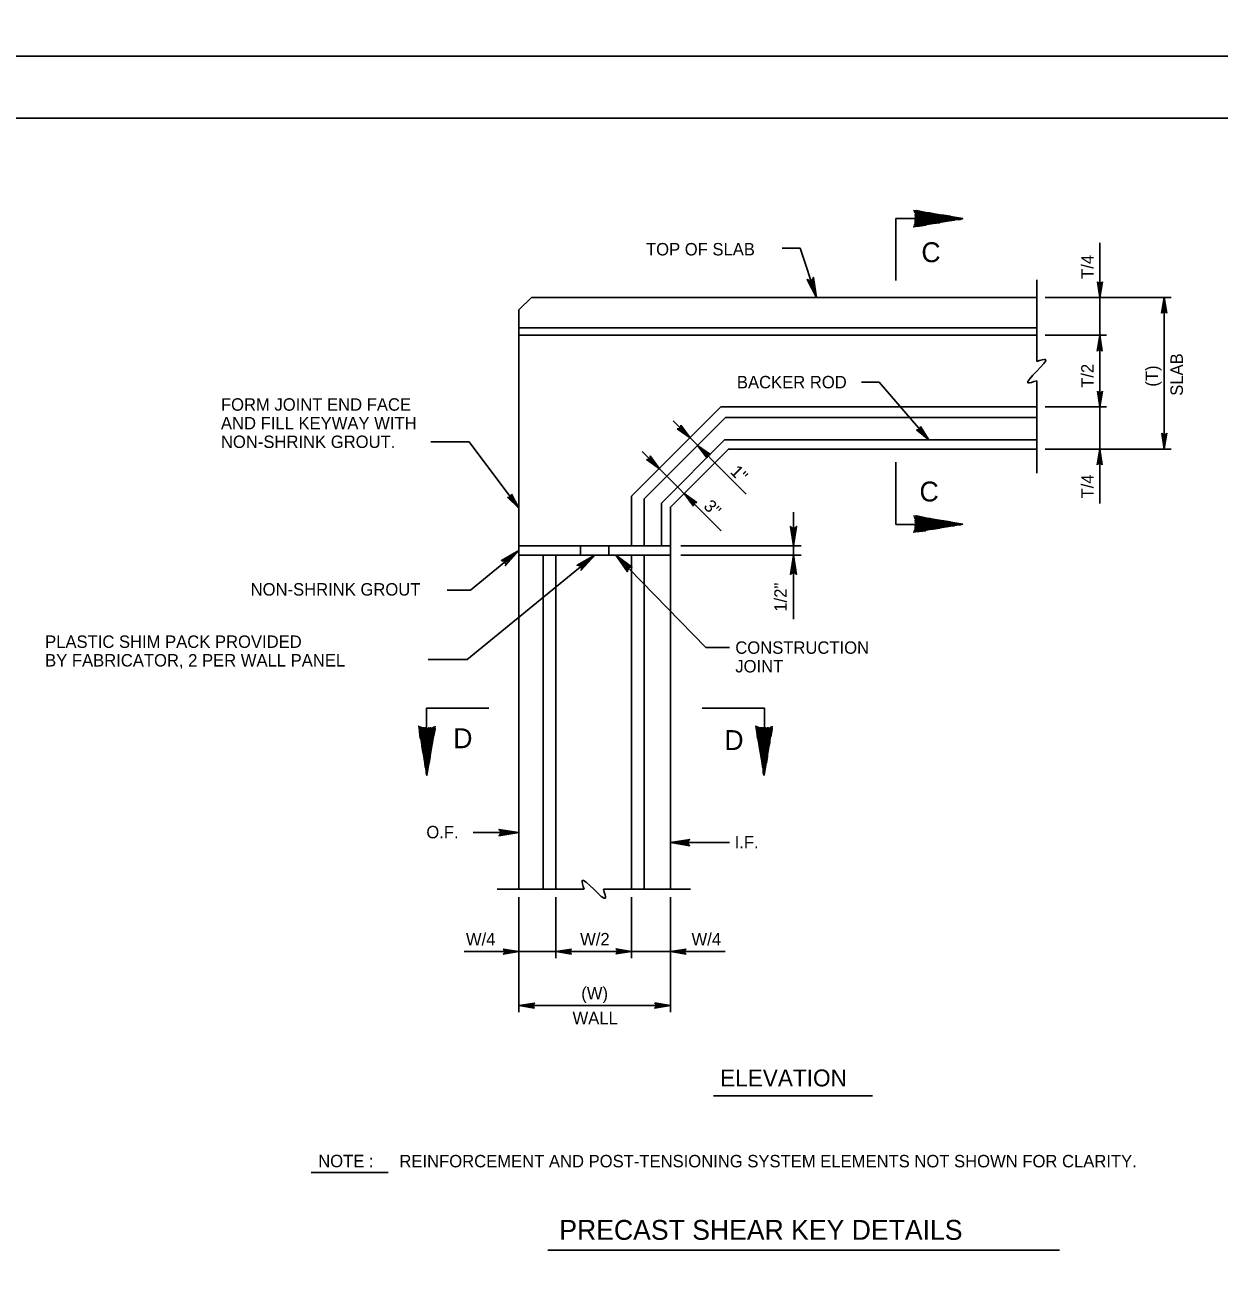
# Model space of a CAD drawing. Extents: x 641328 to 643024, y 298283 to 300065.
# Drawn here: x 641559 to 641847.3, y 298583 to 298884.8 of the extents above; entities that cross this region are included whole.
import ezdxf

# ---------------------------------------------------------------- set-up
doc = ezdxf.new("R2010")
doc.units = 0
for name, color, linetype in [('2', 7, 'Continuous'), ('40', 7, 'Continuous'), ('63', 7, 'Continuous'), ('Default', 7, 'Continuous'), ('PLT-BNDY', 7, 'Continuous')]:
    doc.layers.add(name, color=color, linetype=linetype)

msp = doc.modelspace()

# ---------------------------------------------------------------- linework, layer by layer
at = {"layer": '2'}
for p, q in [((641367.51, 298862.3), (642153.5, 298862.3)), ((641769.25, 298838.11), (641769.25, 298823.08)), ((641769.25, 298838.11), (641784.28, 298838.11)), ((641818.54, 298809.88), (641818.54, 298832.18)), ((641746.21, 298830.93), (641750.15, 298819)), ((641803.33, 298803.54), (641803.33, 298823.25)), ((641818.11, 298822.61), (641817.95, 298822.8)), ((641817.95, 298822.8), (641818.54, 298819)), ((641818.11, 298822.61), (641818.37, 298822.47)), ((641818.54, 298819), (641818.11, 298822.61)), ((641818.37, 298822.47), (641818.54, 298819)), ((641818.37, 298822.47), (641818.74, 298822.47)), ((641818.54, 298819), (641819.17, 298822.8)), ((641819, 298822.6), (641818.54, 298819)), ((641818.54, 298819), (641818.74, 298822.47)), ((641818.54, 298819), (641818.56, 298822.47)), ((641818.74, 298822.47), (641819, 298822.6)), ((641819.17, 298822.8), (641819, 298822.6)), ((641678.26, 298816), (641681.26, 298819)), ((641678.26, 298816), (641678.26, 298676.24)), ((641803.33, 298819), (641681.26, 298819)), ((641805.35, 298819), (641835.74, 298819)), ((641834.11, 298819), (641833.48, 298815.21)), ((641833.65, 298815.4), (641834.11, 298819)), ((641834.11, 298819), (641833.91, 298815.53)), ((641834.11, 298819), (641834.1, 298815.53)), ((641834.11, 298782.43), (641834.11, 298819)), ((641834.28, 298815.53), (641834.11, 298819)), ((641834.11, 298819), (641834.54, 298815.39)), ((641834.7, 298815.2), (641834.11, 298819)), ((641833.48, 298815.21), (641833.65, 298815.4)), ((641833.91, 298815.53), (641833.65, 298815.4)), ((641834.28, 298815.53), (641833.91, 298815.53)), ((641834.54, 298815.39), (641834.28, 298815.53)), ((641834.54, 298815.39), (641834.7, 298815.2)), ((641803.33, 298811.65), (641678.26, 298811.65)), ((641803.33, 298809.88), (641678.26, 298809.88)), ((641805.35, 298809.88), (641820.17, 298809.88)), ((641818.54, 298809.88), (641817.91, 298806.08)), ((641818.08, 298806.28), (641818.54, 298809.88)), ((641818.54, 298809.88), (641818.34, 298806.4)), ((641818.54, 298809.88), (641818.53, 298806.4)), ((641818.54, 298792.58), (641818.54, 298809.88)), ((641818.71, 298806.4), (641818.54, 298809.88)), ((641818.54, 298809.88), (641818.97, 298806.27)), ((641819.13, 298806.07), (641818.54, 298809.88)), ((641817.91, 298806.08), (641818.08, 298806.28)), ((641818.34, 298806.4), (641818.08, 298806.28)), ((641818.71, 298806.4), (641818.34, 298806.4)), ((641818.97, 298806.27), (641818.71, 298806.4)), ((641818.97, 298806.27), (641819.13, 298806.07)), ((641765.24, 298798.56), (641760.96, 298798.56)), ((641777.24, 298784.61), (641765.24, 298798.56)), ((641803.33, 298776.57), (641803.33, 298798.92)), ((641818.11, 298796.19), (641817.95, 298796.38)), ((641817.95, 298796.38), (641818.54, 298792.58)), ((641818.11, 298796.19), (641818.37, 298796.05)), ((641818.54, 298792.58), (641818.11, 298796.19)), ((641818.37, 298796.05), (641818.54, 298792.58)), ((641818.37, 298796.05), (641818.74, 298796.05)), ((641818.54, 298792.58), (641819.17, 298796.37)), ((641819, 298796.18), (641818.54, 298792.58)), ((641818.54, 298792.58), (641818.74, 298796.05)), ((641818.54, 298792.58), (641818.56, 298796.05)), ((641818.74, 298796.05), (641819, 298796.18)), ((641819.17, 298796.37), (641819, 298796.18)), ((641705.47, 298771.04), (641727.01, 298792.58)), ((641803.33, 298792.58), (641727.01, 298792.58)), ((641805.35, 298792.58), (641820.17, 298792.58)), ((641818.54, 298769.31), (641818.54, 298792.58)), ((641708.52, 298770.42), (641728.15, 298790.05)), ((641733.15, 298771.57), (641715.47, 298789.25)), ((641803.33, 298790.05), (641728.15, 298790.05)), ((641719.62, 298785.1), (641716.49, 298787.33)), ((641716.49, 298787.33), (641716.75, 298787.32)), ((641717.03, 298787.41), (641716.75, 298787.32)), ((641716.75, 298787.32), (641719.62, 298785.1)), ((641717.28, 298787.67), (641717.03, 298787.41)), ((641719.62, 298785.1), (641717.03, 298787.41)), ((641719.62, 298785.1), (641717.15, 298787.54)), ((641717.37, 298787.95), (641717.28, 298787.67)), ((641717.28, 298787.67), (641719.62, 298785.1)), ((641717.37, 298787.95), (641717.35, 298788.2)), ((641717.35, 298788.2), (641719.62, 298785.1)), ((641719.62, 298785.1), (641717.37, 298787.95)), ((641777.24, 298784.61), (641774.3, 298787.09)), ((641774.3, 298787.09), (641774.56, 298787.05)), ((641774.84, 298787.12), (641774.56, 298787.05)), ((641774.56, 298787.05), (641777.24, 298784.61)), ((641775.11, 298787.36), (641774.84, 298787.12)), ((641777.24, 298784.61), (641774.84, 298787.12)), ((641777.24, 298784.61), (641774.98, 298787.24)), ((641775.23, 298787.64), (641775.11, 298787.36)), ((641775.11, 298787.36), (641777.24, 298784.61)), ((641775.23, 298787.64), (641775.22, 298787.89)), ((641775.22, 298787.89), (641777.24, 298784.61)), ((641777.24, 298784.61), (641775.23, 298787.64)), ((641833.68, 298786.03), (641833.52, 298786.23)), ((641833.52, 298786.23), (641834.11, 298782.43)), ((641833.68, 298786.03), (641833.95, 298785.9)), ((641834.11, 298782.43), (641833.68, 298786.03)), ((641833.95, 298785.9), (641834.11, 298782.43)), ((641833.95, 298785.9), (641834.31, 298785.9)), ((641834.11, 298782.43), (641834.75, 298786.22)), ((641834.57, 298786.02), (641834.11, 298782.43)), ((641834.11, 298782.43), (641834.31, 298785.9)), ((641834.11, 298782.43), (641834.13, 298785.9)), ((641834.31, 298785.9), (641834.57, 298786.02)), ((641834.75, 298786.22), (641834.57, 298786.02)), ((641657.01, 298784.18), (641666.25, 298784.18)), ((641666.25, 298784.18), (641678.26, 298768.15)), ((641712.65, 298769.33), (641727.93, 298784.61)), ((641723.75, 298780.73), (641721.41, 298783.31)), ((641721.41, 298783.31), (641723.66, 298780.45)), ((641723.68, 298780.2), (641721.41, 298783.31)), ((641721.41, 298783.31), (641724, 298780.99)), ((641724.28, 298781.09), (641721.41, 298783.31)), ((641721.41, 298783.31), (641724.54, 298781.07)), ((641721.41, 298783.31), (641723.87, 298780.86)), ((641803.33, 298784.61), (641727.93, 298784.61)), ((641727.13, 298762.71), (641708.03, 298781.81)), ((641712.18, 298777.66), (641709.05, 298779.89)), ((641709.05, 298779.89), (641709.31, 298779.88)), ((641709.59, 298779.97), (641709.31, 298779.88)), ((641709.31, 298779.88), (641712.18, 298777.66)), ((641709.84, 298780.23), (641709.59, 298779.97)), ((641712.18, 298777.66), (641709.59, 298779.97)), ((641712.18, 298777.66), (641709.71, 298780.1)), ((641709.93, 298780.51), (641709.84, 298780.23)), ((641709.84, 298780.23), (641712.18, 298777.66)), ((641709.93, 298780.51), (641709.91, 298780.76)), ((641709.91, 298780.76), (641712.18, 298777.66)), ((641712.18, 298777.66), (641709.93, 298780.51)), ((641714.83, 298768.43), (641728.83, 298782.43)), ((641728.83, 298782.43), (641714.83, 298768.43)), ((641723.66, 298780.45), (641723.75, 298780.73)), ((641723.66, 298780.45), (641723.68, 298780.2)), ((641723.75, 298780.73), (641724, 298780.99)), ((641724, 298780.99), (641724.28, 298781.09)), ((641724.54, 298781.07), (641724.28, 298781.09)), ((641728.83, 298782.43), (641803.33, 298782.43)), ((641805.35, 298782.43), (641835.74, 298782.43)), ((641818.54, 298782.43), (641817.91, 298778.63)), ((641818.08, 298778.83), (641818.54, 298782.43)), ((641818.54, 298782.43), (641818.34, 298778.95)), ((641818.54, 298782.43), (641818.53, 298778.95)), ((641818.71, 298778.95), (641818.54, 298782.43)), ((641818.54, 298782.43), (641818.97, 298778.82)), ((641819.13, 298778.62), (641818.54, 298782.43)), ((641769.25, 298764.24), (641769.25, 298779.27)), ((641817.91, 298778.63), (641818.08, 298778.83)), ((641818.34, 298778.95), (641818.08, 298778.83)), ((641818.71, 298778.95), (641818.34, 298778.95)), ((641818.97, 298778.82), (641818.71, 298778.95)), ((641818.97, 298778.82), (641819.13, 298778.62)), ((641678.26, 298768.15), (641675.48, 298770.81)), ((641675.48, 298770.81), (641675.73, 298770.76)), ((641676.02, 298770.81), (641675.73, 298770.76)), ((641675.73, 298770.76), (641678.26, 298768.15)), ((641676.31, 298771.03), (641676.02, 298770.81)), ((641678.26, 298768.15), (641676.02, 298770.81)), ((641678.26, 298768.15), (641676.16, 298770.92)), ((641676.44, 298771.3), (641676.31, 298771.03)), ((641676.31, 298771.03), (641678.26, 298768.15)), ((641676.44, 298771.3), (641676.45, 298771.55)), ((641678.26, 298768.15), (641676.44, 298771.3)), ((641676.45, 298771.55), (641678.26, 298768.15)), ((641705.47, 298759.08), (641705.47, 298771.04)), ((641720.46, 298769.14), (641718.12, 298771.71)), ((641718.12, 298771.71), (641720.37, 298768.86)), ((641720.39, 298768.61), (641718.12, 298771.71)), ((641718.12, 298771.71), (641720.71, 298769.4)), ((641720.99, 298769.49), (641718.12, 298771.71)), ((641718.12, 298771.71), (641721.25, 298769.48)), ((641718.12, 298771.71), (641720.59, 298769.27)), ((641708.52, 298759.08), (641708.52, 298770.42)), ((641712.65, 298769.33), (641712.65, 298759.08)), ((641714.83, 298768.43), (641714.83, 298676.24)), ((641720.37, 298768.86), (641720.46, 298769.14)), ((641720.37, 298768.86), (641720.39, 298768.61)), ((641720.46, 298769.14), (641720.71, 298769.4)), ((641720.71, 298769.4), (641720.99, 298769.49)), ((641721.25, 298769.48), (641720.99, 298769.49)), ((641769.25, 298764.24), (641784.28, 298764.24)), ((641714.83, 298759.08), (641678.26, 298759.08)), ((641714.83, 298759.08), (641678.26, 298759.08)), ((641678.26, 298759.08), (641678.26, 298756.82)), ((641714.83, 298756.82), (641714.83, 298759.08)), ((641717.35, 298759.08), (641746.4, 298759.08)), ((641665.78, 298731.63), (641696.55, 298756.82)), ((641666.58, 298748.38), (641678.26, 298757.95)), ((641678.26, 298756.82), (641714.83, 298756.82)), ((641684.13, 298676.14), (641684.13, 298756.82)), ((641687.18, 298676.14), (641687.18, 298756.82)), ((641723.43, 298734.49), (641701.66, 298756.82)), ((641705.47, 298676.14), (641705.47, 298756.82)), ((641708.52, 298676.14), (641708.52, 298756.82)), ((641717.35, 298756.82), (641746.4, 298756.82)), ((641655.96, 298719.85), (641670.99, 298719.85)), ((641655.96, 298719.85), (641655.96, 298704.82)), ((641737.53, 298719.85), (641722.5, 298719.85)), ((641737.53, 298719.85), (641737.53, 298704.82)), ((641667.22, 298689.84), (641678.26, 298689.84)), ((641714.83, 298687.41), (641729.09, 298687.41)), ((641694.01, 298676.14), (641673.02, 298676.14)), ((641678.26, 298674.2), (641678.26, 298646.44)), ((641687.18, 298674.2), (641687.18, 298659.49)), ((641719.68, 298676.14), (641698.64, 298676.14)), ((641705.47, 298674.2), (641705.47, 298659.49)), ((641714.83, 298674.2), (641714.83, 298646.44)), ((641678.26, 298661.12), (641665, 298661.12)), ((641674.65, 298661.55), (641674.46, 298661.71)), ((641674.46, 298661.71), (641678.26, 298661.12)), ((641678.26, 298661.12), (641674.46, 298660.48)), ((641674.46, 298660.48), (641674.66, 298660.66)), ((641674.65, 298661.55), (641674.78, 298661.28)), ((641678.26, 298661.12), (641674.65, 298661.55)), ((641674.66, 298660.66), (641678.26, 298661.12)), ((641674.79, 298660.92), (641674.66, 298660.66)), ((641674.78, 298661.28), (641678.26, 298661.12)), ((641674.78, 298661.28), (641674.79, 298660.92)), ((641678.26, 298661.12), (641674.79, 298660.92)), ((641678.26, 298661.12), (641674.79, 298661.1)), ((641687.18, 298661.12), (641678.26, 298661.12)), ((641690.98, 298661.71), (641687.18, 298661.12)), ((641687.18, 298661.12), (641690.79, 298661.55)), ((641690.66, 298661.28), (641687.18, 298661.12)), ((641687.18, 298661.12), (641705.47, 298661.12)), ((641687.18, 298661.12), (641690.65, 298660.92)), ((641690.78, 298660.66), (641687.18, 298661.12)), ((641687.18, 298661.12), (641690.98, 298660.48)), ((641687.18, 298661.12), (641690.65, 298661.1)), ((641690.66, 298661.28), (641690.65, 298660.92)), ((641690.65, 298660.92), (641690.78, 298660.66)), ((641690.79, 298661.55), (641690.66, 298661.28)), ((641690.98, 298660.48), (641690.78, 298660.66)), ((641690.79, 298661.55), (641690.98, 298661.71)), ((641701.67, 298660.53), (641705.47, 298661.12)), ((641701.86, 298660.69), (641701.67, 298660.53)), ((641705.47, 298661.12), (641701.68, 298661.75)), ((641701.68, 298661.75), (641701.87, 298661.57)), ((641705.47, 298661.12), (641701.86, 298660.69)), ((641701.86, 298660.69), (641702, 298660.95)), ((641702, 298661.31), (641701.87, 298661.57)), ((641701.87, 298661.57), (641705.47, 298661.12)), ((641705.47, 298661.12), (641702, 298661.31)), ((641702, 298660.95), (641702, 298661.31)), ((641705.47, 298661.12), (641702, 298661.13)), ((641702, 298660.95), (641705.47, 298661.12)), ((641705.47, 298661.12), (641714.83, 298661.12)), ((641718.64, 298661.71), (641714.83, 298661.12)), ((641714.83, 298661.12), (641718.44, 298661.55)), ((641718.31, 298661.28), (641714.83, 298661.12)), ((641714.83, 298661.12), (641718.31, 298660.92)), ((641718.43, 298660.66), (641714.83, 298661.12)), ((641714.83, 298661.12), (641718.63, 298660.48)), ((641714.83, 298661.12), (641718.31, 298661.1)), ((641714.83, 298661.12), (641728.09, 298661.12)), ((641718.44, 298661.55), (641718.31, 298661.28)), ((641718.31, 298661.28), (641718.31, 298660.92)), ((641718.31, 298660.92), (641718.43, 298660.66)), ((641718.63, 298660.48), (641718.43, 298660.66)), ((641718.44, 298661.55), (641718.64, 298661.71)), ((641682.06, 298648.65), (641678.26, 298648.06)), ((641678.26, 298648.06), (641681.87, 298648.49)), ((641681.73, 298648.23), (641678.26, 298648.06)), ((641678.26, 298648.06), (641714.83, 298648.06)), ((641678.26, 298648.06), (641681.73, 298647.87)), ((641681.86, 298647.6), (641678.26, 298648.06)), ((641678.26, 298648.06), (641682.05, 298647.43)), ((641678.26, 298648.06), (641681.73, 298648.05)), ((641681.87, 298648.49), (641681.73, 298648.23)), ((641681.73, 298648.23), (641681.73, 298647.87)), ((641681.73, 298647.87), (641681.86, 298647.6)), ((641682.05, 298647.43), (641681.86, 298647.6)), ((641681.87, 298648.49), (641682.06, 298648.65)), ((641711.03, 298647.47), (641714.83, 298648.06)), ((641711.22, 298647.63), (641711.03, 298647.47)), ((641714.83, 298648.06), (641711.04, 298648.7)), ((641711.04, 298648.7), (641711.24, 298648.52)), ((641714.83, 298648.06), (641711.22, 298647.63)), ((641711.22, 298647.63), (641711.36, 298647.9)), ((641711.36, 298648.26), (641711.24, 298648.52)), ((641711.24, 298648.52), (641714.83, 298648.06)), ((641714.83, 298648.06), (641711.36, 298648.26)), ((641711.36, 298647.9), (641711.36, 298648.26)), ((641714.83, 298648.06), (641711.36, 298648.08)), ((641711.36, 298647.9), (641714.83, 298648.06)), ((641628.07, 298607.77), (641646.67, 298607.77)), ((641685.27, 298589.03), (641808.82, 298589.03))]:
    msp.add_line(p, q, dxfattribs=at)
for points in [[(641773.55, 298840.03), (641785.43, 298838.05), (641773.55, 298836.07), (641773.75, 298836.27), (641774.94, 298836.27), (641776.52, 298836.47), (641773.75, 298836.47), (641773.95, 298836.87), (641778.3, 298836.87), (641779.89, 298837.06), (641773.95, 298837.06), (641773.95, 298837.46), (641781.47, 298837.46), (641783.45, 298837.66), (641773.95, 298837.66), (641773.95, 298837.86), (641784.84, 298837.86), (641785.43, 298838.05), (641783.85, 298838.25), (641774.15, 298838.25), (641773.95, 298838.45), (641782.46, 298838.65), (641780.88, 298838.85), (641773.95, 298838.85), (641773.95, 298839.04), (641779.29, 298839.04), (641777.51, 298839.44), (641773.95, 298839.44), (641773.75, 298839.64), (641776.13, 298839.64), (641774.34, 298840.03), (641773.75, 298839.84)], [(641748.16, 298823.2), (641748.53, 298823.14), (641750.15, 298819), (641748.16, 298823.2), (641747.89, 298823.36), (641750.15, 298819), (641748.97, 298823.28), (641749.23, 298823.54), (641750.15, 298819), (641749.36, 298823.85), (641749.23, 298823.54)], [(641773.55, 298766.27), (641785.43, 298764.29), (641773.55, 298762.32), (641773.75, 298762.51), (641774.94, 298762.51), (641776.52, 298762.71), (641773.75, 298762.71), (641773.95, 298763.11), (641778.3, 298763.11), (641779.89, 298763.31), (641773.95, 298763.31), (641773.95, 298763.7), (641781.47, 298763.7), (641783.45, 298763.9), (641773.95, 298763.9), (641773.95, 298764.1), (641784.84, 298764.1), (641785.43, 298764.29), (641783.85, 298764.49), (641774.15, 298764.49), (641773.95, 298764.69), (641782.46, 298764.89), (641780.88, 298765.09), (641773.95, 298765.09), (641773.95, 298765.28), (641779.29, 298765.28), (641777.51, 298765.68), (641773.95, 298765.68), (641773.75, 298765.88), (641776.13, 298765.88), (641774.34, 298766.27), (641773.75, 298766.08)], [(641674.32, 298755.47), (641674.67, 298755.33), (641678.26, 298757.95), (641674.32, 298755.47), (641674.01, 298755.48), (641678.26, 298757.95), (641674.96, 298754.97), (641675.05, 298754.61), (641678.26, 298757.95), (641674.99, 298754.28), (641675.05, 298754.61)], [(641714.83, 298756.82), (641678.26, 298756.82)], [(641692.61, 298754.34), (641692.95, 298754.19), (641696.55, 298756.82), (641692.61, 298754.34), (641692.3, 298754.35), (641696.55, 298756.82), (641693.25, 298753.84), (641693.34, 298753.48), (641696.55, 298756.82), (641693.28, 298753.15), (641693.34, 298753.48)], [(641705.29, 298753.92), (641704.93, 298753.81), (641701.66, 298756.82), (641705.29, 298753.92), (641705.6, 298753.89), (641701.66, 298756.82), (641704.6, 298753.49), (641704.47, 298753.14), (641701.66, 298756.82), (641704.49, 298752.81), (641704.47, 298753.14)], [(641658, 298715.55), (641656.02, 298703.67), (641654.04, 298715.55), (641654.23, 298715.35), (641654.23, 298714.16), (641654.43, 298712.58), (641654.43, 298715.35), (641654.83, 298715.15), (641654.83, 298710.8), (641655.03, 298709.21), (641655.03, 298715.15), (641655.42, 298715.15), (641655.42, 298707.63), (641655.62, 298705.65), (641655.62, 298715.15), (641655.82, 298715.15), (641655.82, 298704.26), (641656.02, 298703.67), (641656.21, 298705.25), (641656.21, 298714.96), (641656.41, 298715.15), (641656.61, 298706.64), (641656.81, 298708.22), (641656.81, 298715.15), (641657.01, 298715.15), (641657.01, 298709.81), (641657.4, 298711.59), (641657.4, 298715.15), (641657.6, 298715.35), (641657.6, 298712.98), (641658, 298714.76), (641657.8, 298715.35)], [(641739.45, 298715.55), (641737.47, 298703.67), (641735.49, 298715.55), (641735.69, 298715.35), (641735.69, 298714.16), (641735.89, 298712.58), (641735.89, 298715.35), (641736.28, 298715.15), (641736.28, 298710.8), (641736.48, 298709.21), (641736.48, 298715.15), (641736.88, 298715.15), (641736.88, 298707.63), (641737.08, 298705.65), (641737.08, 298715.15), (641737.27, 298715.15), (641737.27, 298704.26), (641737.47, 298703.67), (641737.67, 298705.25), (641737.67, 298714.96), (641737.87, 298715.15), (641738.07, 298706.64), (641738.26, 298708.22), (641738.26, 298715.15), (641738.46, 298715.15), (641738.46, 298709.81), (641738.86, 298711.59), (641738.86, 298715.15), (641739.06, 298715.35), (641739.06, 298712.98), (641739.45, 298714.76), (641739.25, 298715.35)], [(641673.65, 298689.26), (641673.82, 298689.6), (641678.26, 298689.84), (641673.65, 298689.26), (641673.41, 298689.06), (641678.26, 298689.84), (641673.82, 298690.06), (641673.66, 298690.39), (641678.26, 298689.84), (641673.41, 298690.61), (641673.66, 298690.39)]]:
    msp.add_lwpolyline(points, dxfattribs=at)
for points in [[(641712.65, 298759.08), (641714.83, 298759.08), (641714.83, 298768.43), (641728.83, 298782.43), (641803.33, 298782.43), (641803.33, 298784.61), (641727.93, 298784.61), (641712.65, 298769.33)], [(641693.15, 298759.08), (641693.15, 298756.82), (641699.94, 298756.82), (641699.94, 298759.08)]]:
    msp.add_lwpolyline(points, close=True, dxfattribs=at)
for points in [[(641803.33, 298798.92), (641801.2, 298798.42), (641805.45, 298804.04), (641803.33, 298803.54)], [(641698.64, 298676.14), (641699.14, 298674.01), (641693.51, 298678.26), (641694.01, 298676.14)]]:
    msp.add_spline(points, degree=3, dxfattribs=at)
at = {"layer": '63'}
for p, q in [((641744.57, 298759.08), (641744.57, 298767.2)), ((641744.57, 298741.32), (641744.57, 298759.08))]:
    msp.add_line(p, q, dxfattribs=at)
for points in [[(641744.02, 298763.51), (641744.34, 298763.34), (641744.57, 298759.08), (641744.02, 298763.51), (641743.82, 298763.74), (641744.57, 298759.08), (641744.78, 298763.34), (641745.1, 298763.5), (641744.57, 298759.08), (641745.31, 298763.74), (641745.1, 298763.5)], [(641745.13, 298752.39), (641744.81, 298752.55), (641744.57, 298756.82), (641745.13, 298752.39), (641745.32, 298752.16), (641744.57, 298756.82), (641744.36, 298752.56), (641744.04, 298752.4), (641744.57, 298756.82), (641743.83, 298752.16), (641744.04, 298752.4)], [(641719.26, 298687.97), (641719.1, 298687.65), (641714.83, 298687.41), (641719.26, 298687.97), (641719.49, 298688.16), (641714.83, 298687.41), (641719.09, 298687.2), (641719.25, 298686.88), (641714.83, 298687.41), (641719.49, 298686.67), (641719.25, 298686.88)]]:
    msp.add_lwpolyline(points, dxfattribs=at)
at = {"layer": 'Default'}
for p, q in [((641746.21, 298830.93), (641741.79, 298830.93)), ((641660.92, 298748.38), (641666.58, 298748.38)), ((641656.33, 298731.63), (641665.78, 298731.63)), ((641723.43, 298734.49), (641729.09, 298734.49)), ((641725.27, 298626.24), (641763.64, 298626.24))]:
    msp.add_line(p, q, dxfattribs=at)
at = {"layer": 'PLT-BNDY'}
for points in [[(641327.51, 299471.3), (642168.51, 299471.3), (642168.51, 298877.3), (641327.51, 298877.3)], [(641327.51, 298877.3), (642168.51, 298877.3), (642168.51, 298283.3), (641327.51, 298283.3)]]:
    msp.add_lwpolyline(points, close=True, dxfattribs=at)

# ---------------------------------------------------------------- texts
at = {"layer": '2'}
for s, height, p in [('TOP OF SLAB', 3, (641708.94, 298829.17)), ('C', 4.8, (641775.45, 298827.54)), ('BACKER ROD', 3, (641730.9, 298797.08)), ('FORM JOINT END FACE', 3, (641606.28, 298791.68)), ('AND FILL KEYWAY WITH', 3, (641606.28, 298787.18)), ('NON-SHRINK GROUT.', 3, (641606.28, 298782.68)), ('C', 4.8, (641775, 298769.77)), ('NON-SHRINK GROUT', 3, (641613.45, 298747.05)), ('PLASTIC SHIM PACK PROVIDED ', 3, (641563.82, 298734.42)), ('CONSTRUCTION', 3, (641730.51, 298732.99)), ('BY FABRICATOR, 2 PER WALL PANEL', 3, (641563.82, 298729.92)), ('JOINT', 3, (641730.51, 298728.49)), ('W/4', 3, (641665.45, 298662.6)), ('W/2', 3, (641693.03, 298662.6)), ('NOTE :', 3, (641629.77, 298609.04)), ('REINFORCEMENT AND POST-TENSIONING SYSTEM ELEMENTS NOT SHOWN FOR CLARITY.', 3, (641649.39, 298609.01)), ('PRECAST SHEAR KEY DETAILS', 4.8, (641688, 298591.51))]:
    msp.add_text(s, height=height, dxfattribs=at).set_placement(p)
for s, height, rotation, p in [('T/4', 3, 90, (641817.05, 298823.5)), ('SLAB', 3, 90, (641838.61, 298795.28)), ('T/2', 3, 90, (641817.05, 298797.2)), ('(T)', 3, 90, (641832.61, 298797.48)), ('1"', 3, 315, (641729.09, 298776.73)), ('T/4', 3, 90, (641817.05, 298770.5)), ('3"', 3, 315, (641722.66, 298768.4)), ('D', 4.8, 360, (641662.4, 298710.2)), ('D', 4.8, 360, (641727.87, 298709.76)), ('W/4', 3, 360, (641719.94, 298662.6)), ('(W)', 3, 360, (641693.31, 298649.56)), ('WALL', 3, 360, (641691.2, 298643.56))]:
    msp.add_text(s, height=height, rotation=rotation, dxfattribs=at).set_placement(p)
at = {"layer": '40'}
msp.add_text('1/2"', height=3, rotation=90, dxfattribs=at).set_placement((641742.93, 298743.16))
at = {"layer": '63'}
for s, p in [('O.F.', (641655.89, 298688.44)), ('I.F.', (641730.36, 298686.04))]:
    msp.add_text(s, height=3, dxfattribs=at).set_placement(p)
at = {"layer": 'Default'}
msp.add_text('ELEVATION', height=4.08, dxfattribs=at).set_placement((641726.84, 298628.55))

doc.saveas('drawing.dxf')
